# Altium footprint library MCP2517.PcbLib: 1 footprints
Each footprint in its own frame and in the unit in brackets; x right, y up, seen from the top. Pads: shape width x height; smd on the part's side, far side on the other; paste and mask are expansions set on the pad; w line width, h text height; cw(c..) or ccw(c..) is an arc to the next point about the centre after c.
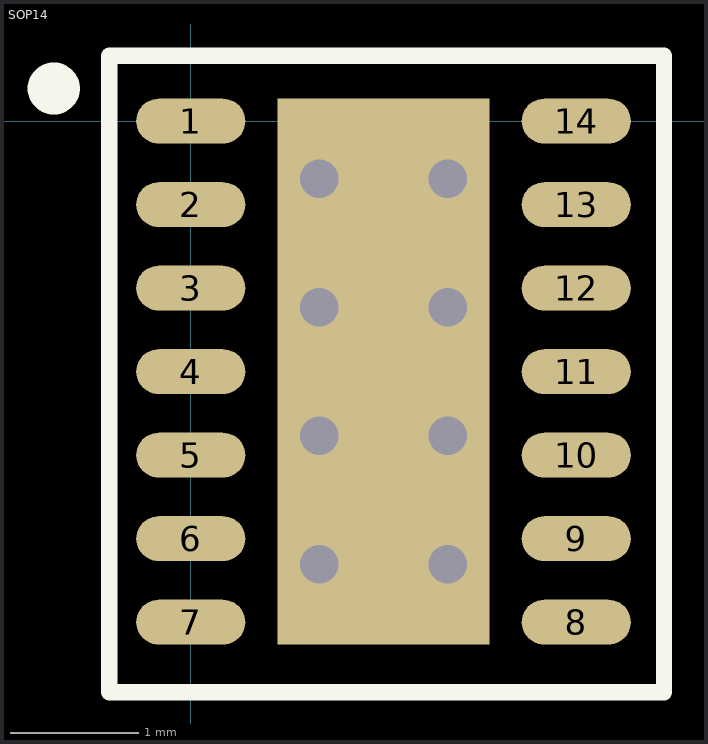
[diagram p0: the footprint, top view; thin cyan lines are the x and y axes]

## SOP14 [mm]
pads (23):
  oval 0.85x0.35 smd: 1(0,0) 2(0,-0.65) 3(0,-1.3) 4(0,-1.95) 5(0,-2.6) 6(0,-3.25) 7(0,-3.9) 8(3,-3.9) 9(3,-3.25) 10(3,-2.6) 11(3,-1.95) 12(3,-1.3) 13(3,-0.65) 14(3,0)
  round 0 hole 0.3: ""(1,-3.45) ""(1,-2.45) ""(1,-1.45) ""(1,-0.45) ""(2,-3.45) ""(2,-2.45) ""(2,-1.45)
  rect 1.65x4.25 smd: ""(1.5,-1.95)
  round 0.3 hole 0.3: ""(2,-0.45)
Top Overlay:
  circle w0.254: c-1.067,0.254 r0.076
  lines w0.127: -0.635,-4.445 3.683,-4.445 3.683,0.508 -0.635,0.508 -0.635,-4.445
